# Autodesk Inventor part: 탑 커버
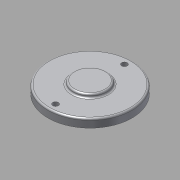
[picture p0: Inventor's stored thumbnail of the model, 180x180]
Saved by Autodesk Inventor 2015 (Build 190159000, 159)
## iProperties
Created: 2017-05
Part Number: 탑 커버
Material: 알루미늄 6061
Document SubType Name: Modeling
Designer: mduedu
Density: 1 g/cm^3
Appearance: 알루미늄 - 평지
Author: mduedu
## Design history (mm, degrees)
sketch "스케치1"
  geometry: C1 r 25 at (0, 0); 1 further point
  constraints: 1 centre point, 1 coincident
  dimensions: "d31" = 50 diameter of C1
extrude "돌출1" new body sketch "스케치1" distance "d2" = 5; taper "d3" = 0 deg
sketch "스케치2"
  geometry: C1 r 10 at (0, 0); 1 further point
  constraints: 1 centre point, 1 coincident
  dimensions: "d5" = 20 diameter of C1
extrude "돌출2" join sketch "스케치2" distance "d6" = 2; taper "d7" = 0 deg
sketch "스케치3"
  geometry: C1 r 16 at (0, 0); 1 further point
  constraints: 1 centre point, 1 coincident
  dimensions: "d32" = 32 diameter of C1
extrude "돌출3" join sketch "스케치3" distance "d10" = 3; taper "d11" = 0 deg
sketch "스케치4"
  geometry: C1 r 16 at (0, 0) reference; C2 r 14 at (0, 0); 1 further point
  constraints: 1 centre point
  dimensions: "d33" = 2 radial gap between concentric circles of C2 C1
extrude "돌출4" cut sketch "스케치4" stored distance "d14" = 2; taper "d15" = 0 deg
chamfer "모따기1" distance "d16" = 1; stored, may be unused: second distance "d17" = 2, angle "d18" = 45 deg
fillet "모깎기3" dims "d19" = 1
fillet "모깎기4" dims "d20" = 1
fillet "모깎기5" dims "d21" = 1
sketch "스케치5" dims "d34" = 41
  geometry: C1 r 25 at (0, 0) reference; 2 further points
  constraints: 2 vertical alignment, 1 coincident, 2 other
hole "구멍2" sketch "스케치5" at (0, 20.5) diameter "d35" = 3.4; stored, may be unused: countersink angle "d39" = 90 deg, drill point angle "d41" = 118 deg; dims "d36" = 6, "d37" = 4, "d38" = 2, "d40" = 8
node "솔리드1"
pattern_circular "원형 패턴1" dims angle "d43" = 360 deg
node "투영된 루프2"
